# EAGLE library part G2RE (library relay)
RELAY 1 x switch, high current, Omron
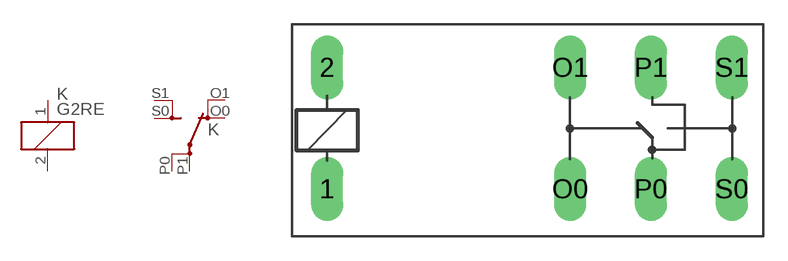
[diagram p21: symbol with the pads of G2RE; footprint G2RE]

Designator prefix K; gates 1=K 2=UD

## G2RE (OC_FARNELL: unknown; OC_NEWARK: unknown)  [G2RE]
1  1:1  pas
2  1:2  pas
O0  2:O  pas
O1  2:O  pas
P0  2:P  pas
P1  2:P  pas
S0  2:S  pas
S1  2:S  pas

## Footprint G2RE (pad centres in mm)
RELAY 1 x switch, high current, Omron
drill 1.321 long: 1 -2.54,-3.683; 2 -2.54,3.81; O0 12.471,-3.683; O1 12.471,3.81; P0 17.45,-3.683; P1 17.45,3.81; S0 22.454,-3.683; S1 22.454,3.81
